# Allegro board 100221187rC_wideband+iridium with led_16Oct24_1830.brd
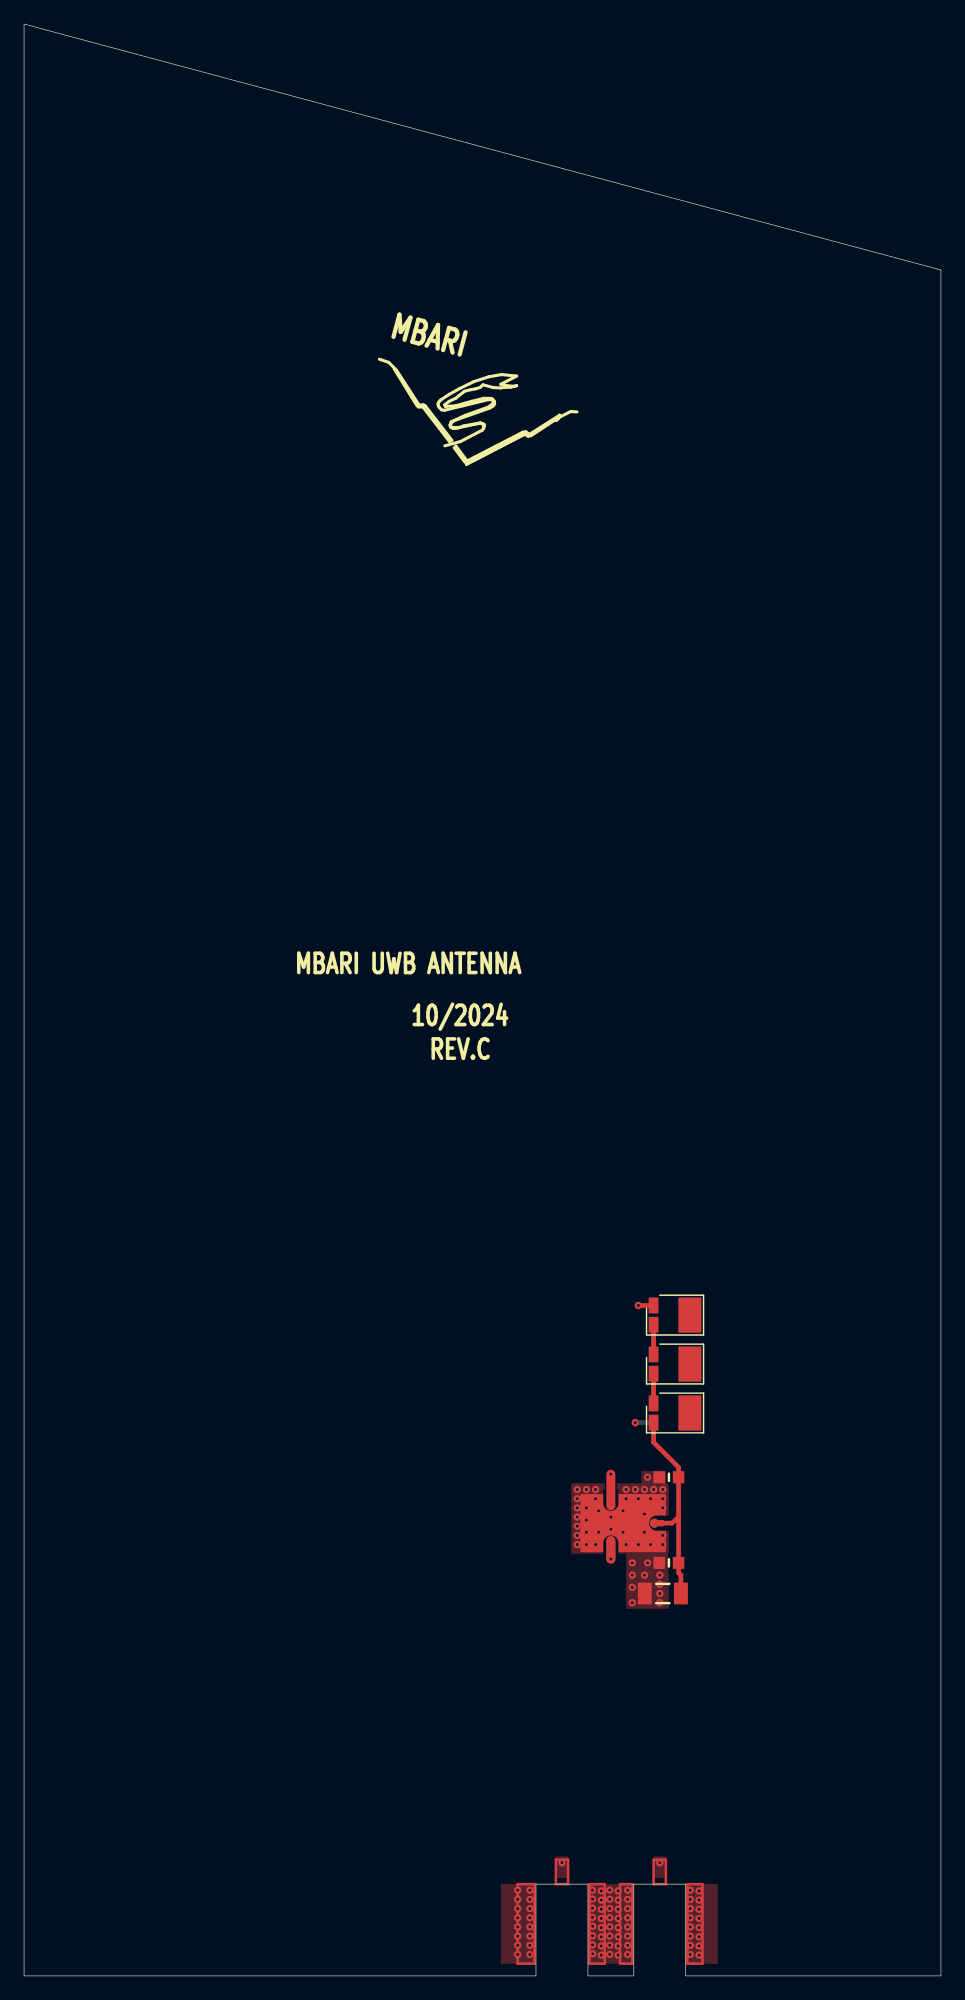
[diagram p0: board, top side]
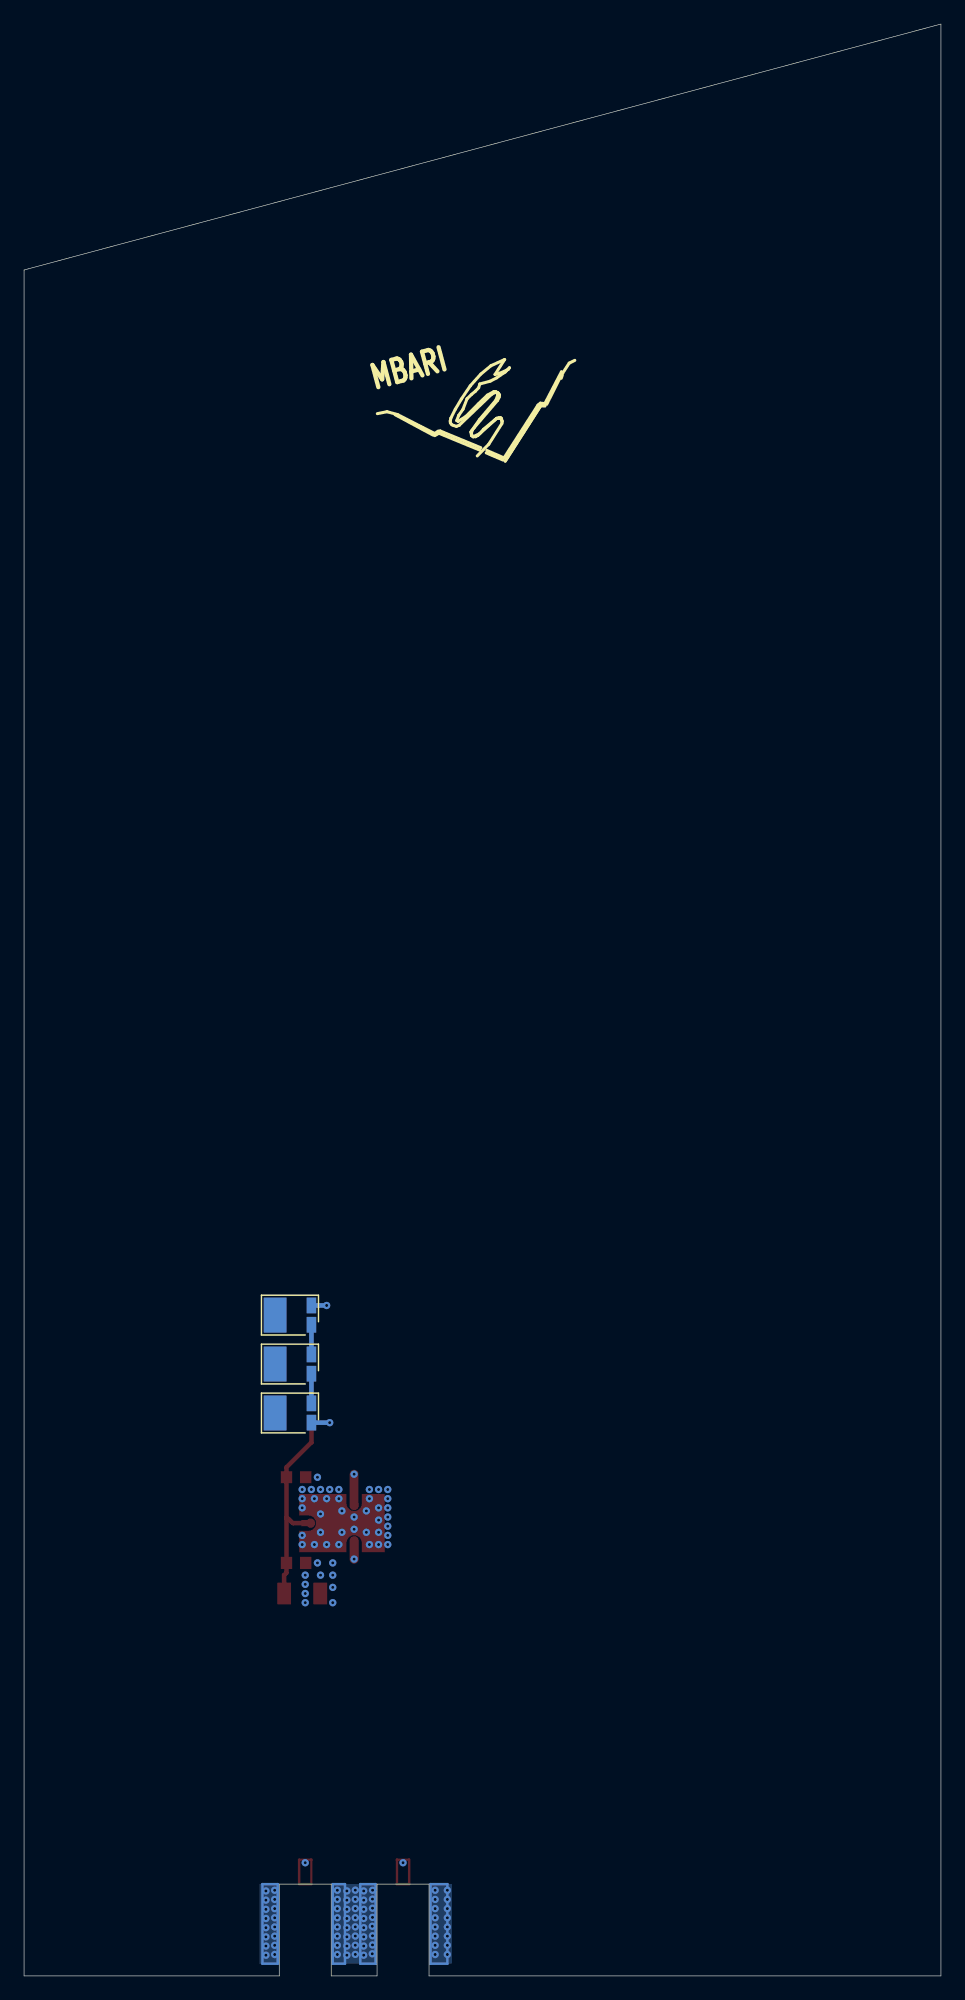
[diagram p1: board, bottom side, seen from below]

Outline 76.2 x 162.05 mm; copper layers: TOP, IN1, IN2, BOTTOM. Coordinates in mm from the lower left corner of the outline.
Outline path: 0,162.05 76.2,141.63 76.2,0 54.99,0 54.99,7.62 50.67,7.62 50.67,0 46.86,0 46.86,7.62 42.55,7.62 42.55,0 0,0 0,162.05

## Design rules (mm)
constraint set DEFAULT: min track width 0.127

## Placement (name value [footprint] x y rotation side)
C1  1.0uF  [CAPC3216X190N]  53.09 31.75 180 top
C2  10,000.0pF  [CAPC1608X87N]  53.59 41.4 180 top
C3  10,000.0pF  [CAPC1608X87N]  53.59 34.29 180 top
D1  LXM2-PH01-0070  [DIODFN449X305X210-3N]  54.1 46.74 0 top
D2  LXM2-PH01-0070  [DIODFN449X305X210-3N]  54.1 50.8 0 top
D3  LXM2-PH01-0070  [DIODFN449X305X210-3N]  54.1 54.86 0 top
D4  LXM2-PH01-0070  [DIODFN449X305X210-3N]  54.1 54.86 0 bottom
D5  LXM2-PH01-0070  [DIODFN449X305X210-3N]  54.1 50.8 0 bottom
D6  LXM2-PH01-0070  [DIODFN449X305X210-3N]  54.1 46.74 0 bottom
NOREF  -  []  71.04 0 90 top
NOREF#2  -  []  86.11 11.43 0 top
NOREF#3  -  []  36.53 0 90 top
NOREF#4  -  []  0 3.13 0 top
NOREF#5  -  []  0 3.01 0 top
NOREF#6  -  []  6.34 0 90 top
NOREF#7  -  []  -116.59 -69.6 0 top
NOREF#8  -  []  -116.59 -69.6 0 top
NOREF#9  -  []  0 1.93 0 top
NOREF#10  -  []  0 3.01 0 top
NOREF#11  -  []  0 3.13 0 top
NOREF#12  -  []  39.12 134.37 345 top
NOREF#13  -  []  38.61 134.62 165 bottom
U1  BT-0014SMG  [MARKI_BTSM-PDSM]  49.78 37.59 0 top

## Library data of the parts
C1-C3 = CAP
D1-D6 = LED_C1A2
U1 = MARKI_BT-0014SMG-1

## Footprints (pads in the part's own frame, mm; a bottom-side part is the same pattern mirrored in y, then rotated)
CAPC1608X87N
  rect 0.95x1.001 smd: 1(-0.8,0) 2(0.8,0)
CAPC3216X190N
  rect 1.151x1.801 smd: 1(-1.501,0) 2(1.501,0)
DIODFN449X305X210-3N
  rect 1.89x2.901 smd: (1.234,0)
  rect 0.79x1.3 smd: 1(-1.786,0.8) 2(-1.786,-0.8)
MARKI_BTSM-PDSM
  custom 0.191x0.191 smd: 1(-1.016,-1.651) 2(-1.016,1.651) 3(2.794,0)
  custom 1.206x1.206 smd: 4(0,0)

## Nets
GND_SIGNAL: C1.2 C2.2 C3.2 D6.1(C) U1.4(GND)
LED: C1.1 C2.1 C3.1 D1.2 U1.3
UWB FEEDLINE: U1.2
N06909: U1.1
N07165: D1.1(C) D2.2
N048171: D2.1(C) D3.2
N048451: D3.1(C) D4.2
N048711: D4.1(C) D5.2
N048971: D5.1(C) D6.2

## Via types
v1: diameter 0.61, hole 0.254, TOP to BOTTOM, 127 vias
v2: diameter 0.61, hole 0.254, IN1 to IN2, 1 via

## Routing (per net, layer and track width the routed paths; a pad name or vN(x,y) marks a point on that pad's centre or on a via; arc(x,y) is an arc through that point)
GND_SIGNAL: length 105.5
  IN1 w1.092: v1(52.83,9.4) 52.83,16.37 arc(53.51,19.78) 55.44,22.66 55.44,22.66 arc(58.77,27.65) 59.94,33.53 59.94,66.42 arc(58.56,70.98) 54.88,74.01 38.56,80.82 arc(35.76,83.47) 35.44,87.32 v2(38.1,96.77)
  BOTTOM w0.381: D6.1 v1(50.8,45.94)
  vias: v1(41.02,7.11) v1(41.02,6.35) v1(41.02,5.59) v1(41.02,4.83) v1(41.02,4.06) v1(41.02,3.3) v1(41.02,2.54) v1(41.02,1.78) v1(42.04,7.11) v1(42.04,6.35) v1(42.04,5.59) v1(42.04,4.83) v1(42.04,4.06) v1(42.04,3.3) v1(42.04,2.54) v1(42.04,1.78) v1(45.97,40.39) v1(45.97,39.62) v1(45.97,38.86) v1(45.97,38.1) v1(45.97,37.34) v1(45.97,36.58) v1(45.97,35.81) v1(46.74,40.39) v1(46.74,38.86) v1(46.74,37.85) v1(46.74,36.83) v1(46.74,35.81) v1(47.24,7.11) v1(47.24,6.38) v1(47.24,5.62) v1(47.24,4.86) v1(47.24,3.34) v1(47.24,2.57) v1(47.26,4.12) v1(47.26,1.84) v1(47.5,40.39) v1(47.5,39.62) v1(47.5,35.81) v1(47.75,38.61) v1(47.75,36.83) v1(47.97,7.05) v1(47.97,6.29) v1(47.97,5.53) v1(47.97,4.77) v1(47.97,4.01) v1(47.97,3.24) v1(47.97,2.48) v1(47.97,1.72) v1(48.67,7.12) v1(48.67,6.36) v1(48.67,5.6) v1(48.67,4.83) v1(48.67,4.07) v1(48.67,3.31) v1(48.67,2.55) v1(48.67,1.79) v1(48.77,38.1) v1(48.77,37.08) v1(49.37,7.05) v1(49.37,6.29) v1(49.37,5.53) v1(49.37,4.77) v1(49.37,4.01) v1(49.37,3.24) v1(49.37,2.48) v1(49.37,1.72) v1(49.78,38.61) v1(49.78,36.83) v1(50.04,40.39) v1(50.04,39.62) v1(50.04,35.81) v1(50.16,7.11) v1(50.16,6.35) v1(50.16,5.59) v1(50.16,4.83) v1(50.16,4.06) v1(50.16,3.3) v1(50.16,2.54) v1(50.16,1.78) v1(50.55,34.29) v1(50.55,33.27) v1(50.55,32.26) v1(50.55,30.99) v1(50.8,40.39) v1(51.05,39.62) v1(51.05,35.81) v1(51.56,40.39) v1(51.56,38.35) v1(51.56,36.83) v1(51.56,33.27) v1(51.82,41.4) v1(51.82,34.29) v1(52.07,39.62) v1(52.07,35.81) v1(52.32,40.39) v1(52.83,33.27) v1(52.83,32.51) v1(52.83,31.75) v1(52.83,30.99) v1(53.09,40.39) v1(53.09,39.62) v1(53.09,38.86) v1(53.09,36.58) v1(53.09,35.81) v1(55.37,7.11) v1(55.37,6.35) v1(55.37,5.59) v1(55.37,4.83) v1(55.37,4.06) v1(55.37,3.3) v1(55.37,2.54) v1(55.37,1.78) v1(56.1,7.05) v1(56.1,6.29) v1(56.1,5.53) v1(56.1,4.77) v1(56.1,4.01) v1(56.1,3.24) v1(56.1,2.48) v1(56.1,1.72)
LED: length 17.1
  TOP w0.381: 54.39,38.04 54.34,38.04 53.85,37.59 U1.3 ; 54.39,38.04 C3.1 54.39,33.47 54.59,33.28 C1.1 ; 54.39,38.04 C2.1 54.39,42.22 52.32,44.3 D1.2
UWB FEEDLINE: length 73.1
  TOP w0.737: U1.2 v1(48.77,41.66)
  IN1 w1.092: 28.7,103.12 24.76,88.23 arc(24.79,76.33) 30.74,66.03 44.28,52.5 arc(47.6,47.53) 48.77,41.66
N06909: length 28.2
  TOP w0.762: U1.1 v1(48.77,34.61)
  IN1 w1.092: v1(48.77,34.61) 48.77,34.88 arc(48.24,32.22) 46.74,29.97 arc(45.23,27.72) 44.7,25.07 v1(44.7,9.4)
N07165: length 2.5
  TOP w0.381: D2.2 D1.1
N048171: length 2.5
  TOP w0.381: D3.2 D2.1
N048451: length 2.5
  TOP w0.381: v1(51.05,55.66) D3.1
  BOTTOM w0.381: D3.1 v1(51.05,55.66)
N048711: length 2.5
  BOTTOM w0.381: D4.1 D5.2
N048971: length 2.5
  BOTTOM w0.381: D5.1 D6.2

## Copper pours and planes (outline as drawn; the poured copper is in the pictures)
GND_SIGNAL on TOP: 42.55,1.02 42.55,7.62 39.62,7.62 39.62,1.02
GND_SIGNAL on TOP: 46.86,7.62 46.86,1.02 50.67,1.02 50.67,7.62
GND_SIGNAL on TOP: 50.04,30.48 50.04,35.05 45.47,35.05 45.47,40.89 51.31,40.89 51.31,41.91 53.34,41.91 53.34,40.89 53.59,40.89 53.59,30.48
GND_SIGNAL on TOP: 53.34,8.13 52.32,8.13 52.32,9.91 53.34,9.91
GND_SIGNAL on TOP: 54.99,7.62 54.99,1.02 57.66,1.02 57.66,7.62
GND_SIGNAL on BOTTOM: 40.64,7.62 40.64,1.02 42.55,1.02 42.55,7.62
GND_SIGNAL on BOTTOM: 46.86,1.02 46.86,7.62 50.67,7.62 50.67,1.02
GND_SIGNAL on BOTTOM: 54.99,7.62 54.99,1.02 56.64,1.02 56.64,7.62
GND_SIGNAL on IN2: 62.3,83.82 62.68,83.82 62.74,1.31 62.74,1.02 54.99,1.02 54.99,7.62 50.67,7.62 50.67,1.02 46.86,1.02 46.86,7.62 42.55,7.62 42.55,1.02 13.72,1.02 13.72,14.58 13.72,14.58 13.72,106.75 29.98,102.39 29.8,101.72 62.88,92.86 62.03,89.67 31.97,97.72 30.52,92.33 62.3,83.81 ; 2 cut-outs
UWB FEEDLINE on IN1: 62.2,131.03 13.77,144.01 28.64,102.66
N06909 on TOP: 45.21,8.13 44.2,8.13 44.2,9.91 45.21,9.91

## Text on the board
User.Comments: rev B | Origin | REV C: D.THOMPSON
Ref Des/Silkscreen Top: MBARI UWB ANTENNA | 10/2024 | REV.C
XSECTION_CHART: *  PLATING: ENIG | L1: TOP CONDUCTOR - COPPER 2.1 MIL | *  DIELECTRIC - 4003C 32 mil | L2: IN1 CONDUCTOR - COPPER 1.4 MIL | *  DIELECTRIC - 4003C 20 mil | L3: IN2 CONDUCTOR - COPPER 1.4 MIL | L4: BOTTOM CONDUCTOR - COPPER 2.1 MIL | DESIGN CROSS SECTION CHART | ___________________________ | TOTAL THICKNESS 93 MIL | 1-4 | 2-3
PAGE_OUTLINE: WIDEN CABLE INPUT SLOTS | ENLARGE OUTLINE, | c
DIMENSION: (2x) ADD EDGE PLATING INSIDE | BOTH SLOTS.
DEVICE_TYPE_BOTTOM: FIGURE | FINISHED_SIZE | 10.0 | DRILL CHART: TOP to BOTTOM | ALL UNITS ARE IN MILS | PLATED | QTY | 127
DEVICE_TYPE_TOP: FIGURE | FINISHED_SIZE | 10.0 | DRILL CHART: IN1 to IN2 | ALL UNITS ARE IN MILS | PLATED | QTY | 1
